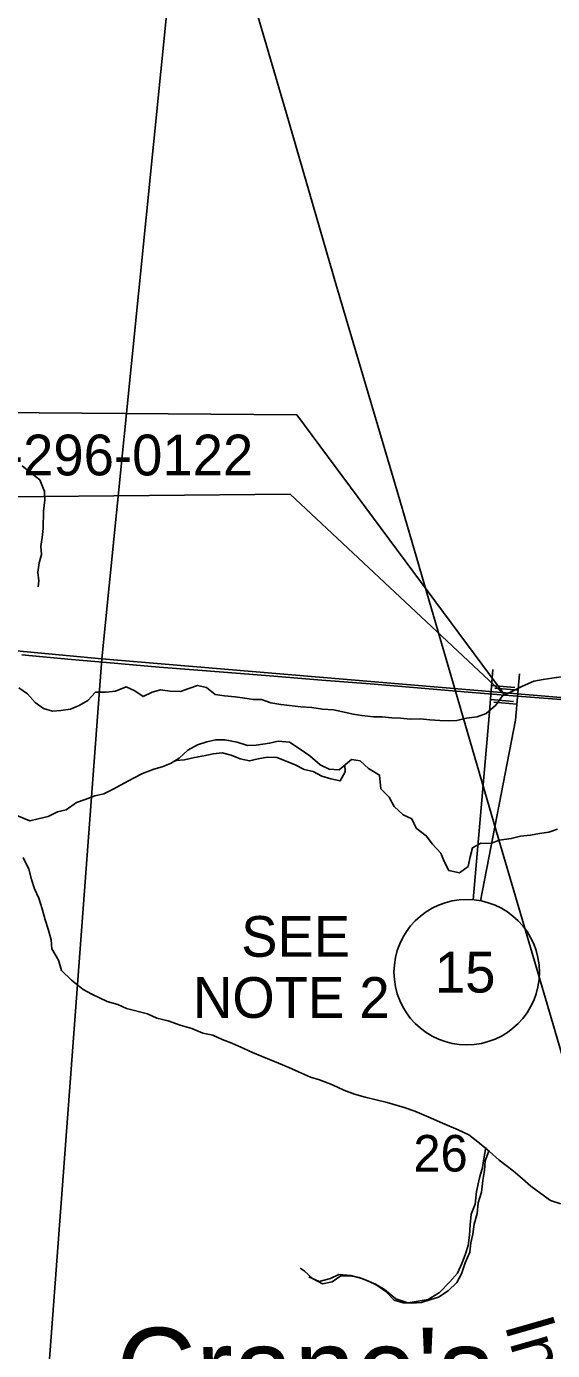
# Model space of a CAD drawing. Extents: x 0 to 1067, y 0 to 440.
# Drawn here: x 297.2 to 333.4, y 257.7 to 348.7 of the extents above; entities that cross this region are included whole.
import ezdxf

# ---------------------------------------------------------------- set-up
doc = ezdxf.new("R2010")
doc.units = 0
for name, color, linetype in [('GM_X_Minor_Lake', 7, 'Continuous'), ('GM_X_Minor_River', 7, 'Continuous'), ('GM_X_Minor_River_Text', 7, 'Continuous'), ('GM_X_Rail_Line', 7, 'Continuous'), ('GM_X_Rail_Line_Text', 7, 'Continuous'), ('GM_X_Section', 7, 'Continuous'), ('GM_X_Section_Text', 7, 'Continuous'), ('GM_X_State_Route', 7, 'Continuous'), ('SH_Masking', 7, 'Continuous'), ('SH_Text', 7, 'Continuous'), ('SN_P_Signs', 7, 'Continuous')]:
    doc.layers.add(name, color=color, linetype=linetype)

msp = doc.modelspace()

# ---------------------------------------------------------------- linework, layer by layer
at = {"layer": 'GM_X_Minor_Lake'}
for points in [[(319.121, 297.922), (318.716, 297.58), (318.034, 297.623), (317.429, 297.938), (316.718, 298.553), (315.982, 299.055), (315.311, 299.486), (314.539, 299.554), (313.943, 299.412), (313.028, 299.279), (312.412, 299.252), (311.713, 299.478), (310.853, 299.641), (310.238, 299.659), (309.62, 299.518), (308.976, 299.308), (308.328, 298.939), (307.719, 298.386), (307.36, 298.156)], [(307.36, 298.156), (307.51, 298.232), (308.081, 298.284), (308.768, 298.424), (309.409, 298.542), (310.073, 298.682), (310.69, 298.755), (311.3, 298.6), (311.908, 298.353), (312.564, 298.197), (313.16, 298.339), (313.778, 298.458), (314.438, 298.438), (315.091, 298.19), (315.698, 297.921), (316.326, 297.605), (316.937, 297.473), (317.543, 297.158), (318.152, 296.957), (318.785, 296.824), (319.145, 297.453), (319.121, 297.922)]]:
    msp.add_lwpolyline(points, dxfattribs=at)
at = {"layer": 'GM_X_Minor_River'}
for points in [[(296.922, 318.485), (297.545, 317.987), (298.146, 317.512), (298.465, 316.726), (298.493, 316.155), (298.402, 315.358), (298.367, 314.172), (298.304, 313.557), (298.218, 312.966), (298.247, 312.394), (298.093, 311.805), (298.006, 311.168), (298.08, 310.572), (298.022, 310.162)], [(324.965, 301.026), (325.646, 300.983), (326.215, 300.966), (326.807, 300.972), (327.472, 301.135), (328.204, 301.227), (328.825, 301.46), (329.502, 302.034), (329.954, 302.683), (330.6, 302.96), (331.339, 303.327), (332.1, 303.67), (332.764, 303.787), (333.359, 303.884), (333.999, 303.979)], [(296.703, 303.213), (297.306, 302.806), (297.813, 302.22), (298.393, 301.792), (299.025, 301.613), (299.595, 301.665), (300.259, 301.76), (300.858, 302.016), (301.437, 302.341), (301.977, 302.919), (302.706, 302.921), (303.346, 302.993), (304.083, 303.291), (304.667, 303.022), (305.247, 302.617), (305.871, 302.918), (306.445, 303.084), (307.103, 302.996), (307.808, 302.975), (308.383, 303.186), (308.981, 303.374), (309.614, 303.241), (310.193, 302.767), (310.85, 302.679), (311.577, 302.612), (312.235, 302.524), (312.824, 302.415), (313.393, 302.421), (314.024, 302.196), (314.704, 302.085), (315.316, 301.998), (316.088, 301.907), (316.838, 301.862), (317.586, 301.748), (318.336, 301.703), (318.969, 301.57), (319.693, 301.411), (320.283, 301.325), (321.077, 301.233), (321.692, 301.238), (322.35, 301.172), (322.941, 301.132), (323.622, 301.066), (324.329, 301.091), (324.965, 301.026)], [(296.292, 294.568), (297.461, 294.076), (298.035, 294.219), (298.722, 294.382), (299.369, 294.705), (299.943, 294.848), (300.663, 295.352), (301.261, 295.54), (301.929, 295.794), (302.547, 295.936), (303.241, 296.28), (303.935, 296.671), (304.629, 297.039), (305.207, 297.341), (305.99, 297.638), (306.564, 297.804), (307.139, 298.015), (307.719, 298.386), (308.328, 298.939), (308.976, 299.308), (309.62, 299.518), (310.238, 299.659), (310.853, 299.641), (311.713, 299.478), (312.412, 299.252), (313.028, 299.279), (313.943, 299.412), (314.539, 299.554), (315.311, 299.486), (315.982, 299.055), (316.718, 298.553), (317.429, 297.938), (318.034, 297.623), (318.716, 297.58), (319.58, 298.308), (320.169, 298.199), (320.746, 297.68), (321.506, 297.223), (321.593, 296.284), (322.168, 295.718), (322.514, 295.068), (323.135, 294.502), (323.718, 294.21), (324.019, 293.585), (324.709, 293.061), (325.148, 292.477), (325.722, 291.866), (325.955, 291.288), (326.256, 290.662), (327.003, 290.503), (327.585, 290.943), (327.74, 291.601), (327.896, 292.236), (328.474, 292.538), (329.156, 292.518), (329.732, 292.752), (330.555, 292.865), (331.198, 293.028), (331.883, 293.099), (332.501, 293.218), (333.141, 293.313), (333.739, 293.501)], [(297, 291.554), (297.387, 290.766), (297.571, 290.053), (297.78, 289.407), (298.08, 288.758), (298.31, 288.043), (298.515, 287.283), (298.724, 286.637), (298.93, 285.9), (298.98, 285.282), (299.436, 284.515), (299.643, 283.8), (300.329, 283.14), (301.13, 282.477), (301.713, 282.162), (302.769, 281.674), (303.513, 281.446), (304.097, 281.178), (305.544, 280.815), (306.196, 280.521), (306.965, 280.338), (307.798, 280.039), (308.589, 279.81), (309.353, 279.491), (310.033, 279.356), (310.684, 279.04), (311.337, 278.792), (312.168, 278.425), (312.775, 278.155), (313.428, 277.884), (314.553, 277.417), (315.273, 277.121), (315.924, 276.828), (316.756, 276.46), (317.366, 276.282), (318.266, 275.936), (319.053, 275.569), (319.773, 275.297), (320.519, 275.092), (322.034, 274.727), (323.184, 274.373), (323.929, 274.122), (325.053, 273.632), (325.84, 273.311), (326.897, 272.846), (327.638, 272.504), (328.262, 272.028), (329.062, 271.342), (329.727, 270.751), (330.685, 270.014), (331.329, 269.469), (331.907, 268.972), (332.598, 268.472), (333.267, 267.995), (333.966, 267.746)], [(329.011, 271.385), (328.77, 270.711), (328.728, 270.049), (328.594, 269.368), (328.502, 268.548), (328.276, 267.824), (328.209, 267.095), (328.005, 266.347), (327.917, 265.664), (327.786, 265.074), (327.699, 264.436), (327.381, 263.692), (327.132, 262.945), (326.818, 262.338), (326.21, 261.785), (325.559, 261.347), (324.962, 261.159), (324.387, 260.971), (323.703, 260.923), (323.134, 260.94), (322.502, 261.141), (321.927, 261.729), (321.325, 262.159), (320.696, 262.452), (320.111, 262.697), (319.477, 262.808), (318.839, 262.804), (318.235, 262.388), (317.571, 262.248), (316.899, 262.633), (316.322, 263.153), (316.054, 263.344)], [(328.812, 271.62), (328.669, 270.849), (328.592, 270.259), (328.376, 269.534), (328.18, 268.604), (328.076, 267.741), (327.793, 267.041), (327.737, 266.313), (327.68, 265.609), (327.601, 264.882), (327.387, 264.248), (327.151, 263.66), (326.868, 262.982), (326.337, 262.399), (325.622, 261.658), (324.843, 261.17), (324.025, 261.045), (323.456, 260.94), (322.621, 261.226), (321.837, 261.874), (321.23, 262.225), (320.283, 262.626), (319.537, 262.819), (318.699, 262.899), (318.127, 262.612), (317.353, 262.419), (316.632, 262.726)]]:
    msp.add_lwpolyline(points, dxfattribs=at)
at = {"layer": 'GM_X_Rail_Line'}
msp.add_lwpolyline([(342.365, 249.574), (338.217, 263.737), (337.689, 265.748), (337.329, 266.901), (336.393, 269.978), (332.907, 281.875), (329.709, 292.779), (322.892, 316.112), (318.543, 330.84), (315.076, 342.778), (302.527, 385.537)], dxfattribs=at)
at = {"layer": 'GM_X_Section'}
for points in [[(308.5, 365.904), (302.416, 305.207), (240.782, 310.986), (246.65, 370.913)], [(308.5, 365.904), (371.523, 360.332), (365.534, 299.905), (302.416, 305.207)], [(240.782, 310.986), (302.416, 305.207), (297.822, 243.897), (235.406, 252.097)], [(302.416, 305.207), (365.534, 299.905), (359.758, 238.612), (297.822, 243.897)]]:
    msp.add_lwpolyline(points, close=True, dxfattribs=at)
at = {"layer": 'GM_X_State_Route'}
msp.add_lwpolyline([(296.907, 305.48), (300.323, 305.175), (302.737, 304.967), (306.338, 304.649), (309.013, 304.432), (311.949, 304.203), (314.513, 303.994), (317.524, 303.759), (320.868, 303.488), (323.84, 303.238), (327.593, 302.935), (330.974, 302.657), (333.391, 302.473), (336.549, 302.205)], dxfattribs=at)
at = {"layer": 'SH_Masking'}
msp.add_circle((327.495, 283.678), 5, dxfattribs=at)
at = {"layer": 'SH_Text'}
for p, q in [((327.931, 288.659), (329.037, 301.301)), ((328.446, 288.587), (330.851, 300.994))]:
    msp.add_line(p, q, dxfattribs=at)
msp.add_lwpolyline([(330.109, 302.729), (315.812, 321.98), (286.28, 322.208), (286.245, 316.252), (315.363, 316.534)], close=True, dxfattribs=at)
msp.add_circle((327.495, 283.678), 5, dxfattribs=at)
at = {"layer": 'SN_P_Signs'}
for p, q in [((329.037, 301.301), (329.303, 304.489)), ((330.851, 300.994), (331.118, 304.182)), ((329.21, 303.373), (330.804, 303.24)), ((331.025, 303.066), (329.43, 303.2)), ((329.13, 302.417), (330.724, 302.283)), ((329.17, 302.895), (329.17, 302.895)), ((329.17, 302.895), (329.17, 302.895)), ((330.945, 302.11), (329.35, 302.243)), ((330.985, 302.588), (330.985, 302.588)), ((330.985, 302.588), (330.985, 302.588))]:
    msp.add_line(p, q, dxfattribs=at)

# ---------------------------------------------------------------- texts
at = {"layer": 'GM_X_Minor_River_Text'}
msp.add_text("Crane's", height=5.6819, rotation=0.01531, dxfattribs=at).set_placement((303.391, 253.551))
at = {"layer": 'GM_X_Rail_Line_Text'}
msp.add_text('Indiana', height=3.3977, rotation=285.99788, dxfattribs=at).set_placement((330.075, 259.453))
at = {"layer": 'GM_X_Section_Text'}
msp.add_text('26', height=2.5114, rotation=0.00001, dxfattribs=at).set_placement((323.829, 269.976))
at = {"layer": 'SH_Text'}
for s, p in [('CHP-296-0122', (287.841, 317.827)), ('SEE', (311.987, 284.736)), ('15', (325.308, 282.278)), ('NOTE 2', (308.676, 280.536))]:
    msp.add_text(s, height=2.8, dxfattribs=at).set_placement(p)

doc.saveas('drawing.dxf')
